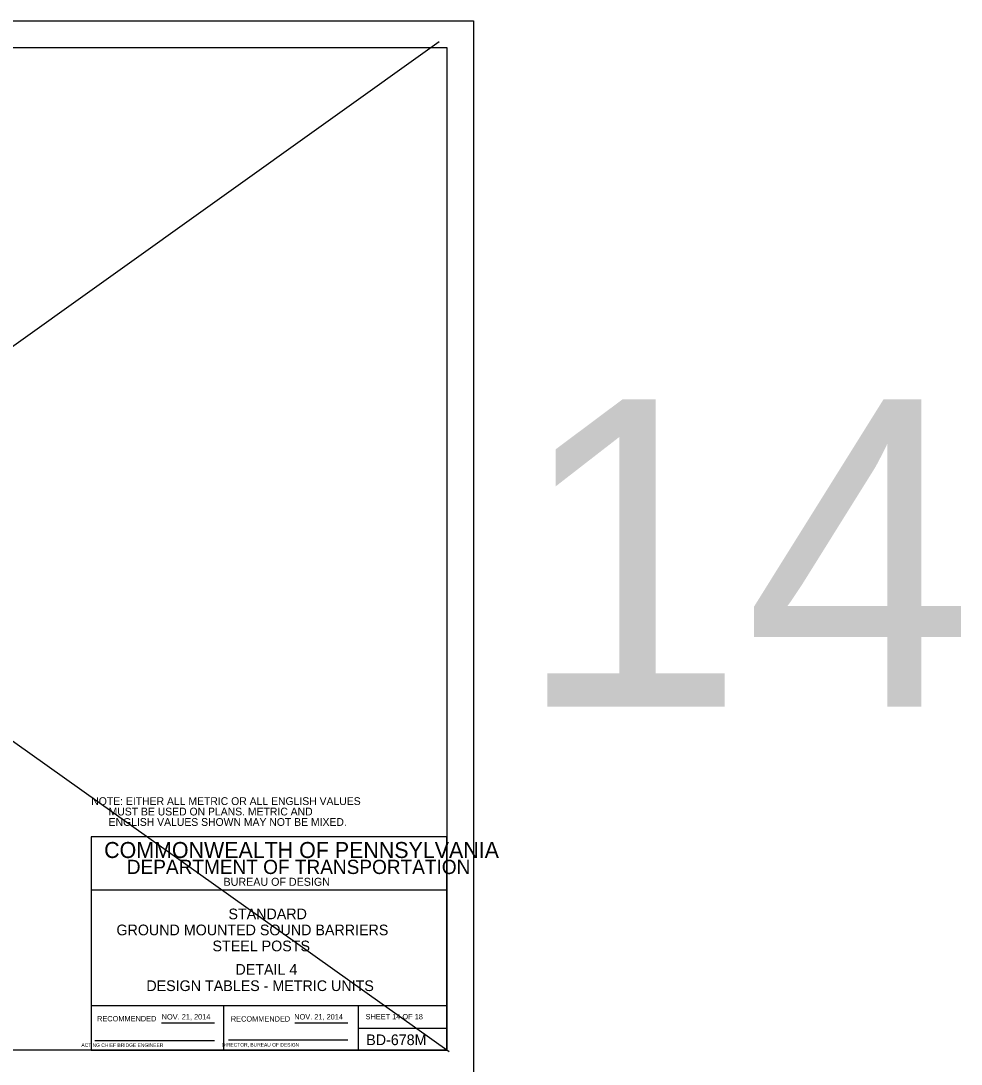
# Model space of a CAD drawing. Extents: x 3475 to 6558, y -3780 to 1166.
# Drawn here: x 6030 to 6558, y -2391 to -1804 of the extents above; entities that cross this region are included whole.
import ezdxf

# ---------------------------------------------------------------- set-up
doc = ezdxf.new("R2010")
doc.units = 0
for name, color, linetype in [('1', 7, 'Continuous'), ('2', 7, 'Continuous'), ('PLT-BNDY', 7, 'Continuous')]:
    doc.layers.add(name, color=color, linetype=linetype)

msp = doc.modelspace()

# ---------------------------------------------------------------- linework, layer by layer
at = {"layer": '1'}
for p, q in [((5475.33, -1818.42), (6270.57, -2383.94)), ((6264.9, -1816.14), (5834.53, -2123.87))]:
    msp.add_line(p, q, dxfattribs=at)
at = {"layer": '2'}
for p, q in [((5483.34, -1819.31), (6269.34, -1819.31)), ((6269.34, -1819.31), (6269.34, -2383.31)), ((6269.34, -2263.31), (6069.34, -2263.31)), ((6069.34, -2263.31), (6069.34, -2383.31)), ((6269.34, -2383.31), (6269.34, -2263.31)), ((6269.34, -2293.31), (6069.34, -2293.31)), ((6269.34, -2358.31), (6069.34, -2358.31)), ((6143.84, -2383.31), (6143.84, -2358.31)), ((6219.34, -2358.31), (6219.34, -2383.31)), ((6108.81, -2367.81), (6138.57, -2367.81)), ((6183.81, -2367.81), (6213.71, -2367.81)), ((6219.34, -2370.81), (6269.34, -2370.81)), ((6071.34, -2377.81), (6138.57, -2377.81)), ((6146.47, -2377.43), (6213.71, -2377.43)), ((6269.34, -2383.31), (5483.34, -2383.31)), ((6069.34, -2383.31), (6269.34, -2383.31))]:
    msp.add_line(p, q, dxfattribs=at)
at = {"layer": 'PLT-BNDY'}
msp.add_lwpolyline([(5443.34, -1804.31), (6284.34, -1804.31), (6284.34, -2398.31), (5443.34, -2398.31)], close=True, dxfattribs=at)

# ---------------------------------------------------------------- texts
at = {"layer": '1'}
for s, height, p in [('14', 172.802, (6308.23, -2190.04)), ('STANDARD', 6, (6146.48, -2309.64)), ('GROUND MOUNTED SOUND BARRIERS', 6.0001, (6083.5, -2318.64)), ('STEEL POSTS', 6.0001, (6137.5, -2327.64)), ('DETAIL 4', 6, (6150.43, -2340.81)), ('DESIGN TABLES - METRIC UNITS', 6.0001, (6100.31, -2350.01)), ('SHEET 14 OF 18', 3, (6223.59, -2365.92)), ('BD-678M', 6, (6223.97, -2380.43))]:
    msp.add_text(s, height=height, dxfattribs=at).set_placement(p)
at = {"layer": '2'}
for s, height, p in [('NOTE: EITHER ALL METRIC OR ALL ENGLISH VALUES', 4.375, (6069.34, -2245.37)), ('      MUST BE USED ON PLANS. METRIC AND', 4.375, (6069.34, -2251.24)), ('      ENGLISH VALUES SHOWN MAY NOT BE MIXED.', 4.375, (6069.34, -2257.12)), ('COMMONWEALTH OF PENNSYLVANIA', 9, (6076.59, -2275.18)), ('DEPARTMENT OF TRANSPORTATION', 8.0002, (6089.34, -2284.18)), ('BUREAU OF DESIGN', 4.5, (6143.72, -2290.81)), ('NOV. 21, 2014', 3, (6108.94, -2366)), ('NOV. 21, 2014', 3, (6183.48, -2366)), ('       ACTING CHIEF BRIDGE ENGINEER', 2.0002, (6058.43, -2381.43))]:
    msp.add_text(s, height=height, dxfattribs=at).set_placement(p)
for s, height, p in [('RECOMMENDED', 3, (6072.61, -2367.06)), ('RECOMMENDED', 3, (6147.83, -2367.18)), ('   DIRECTOR, BUREAU OF DESIGN', 2.0002, (6140.54, -2381.25))]:
    msp.add_text(s, height=height, rotation=360, dxfattribs=at).set_placement(p)

doc.saveas('drawing.dxf')
